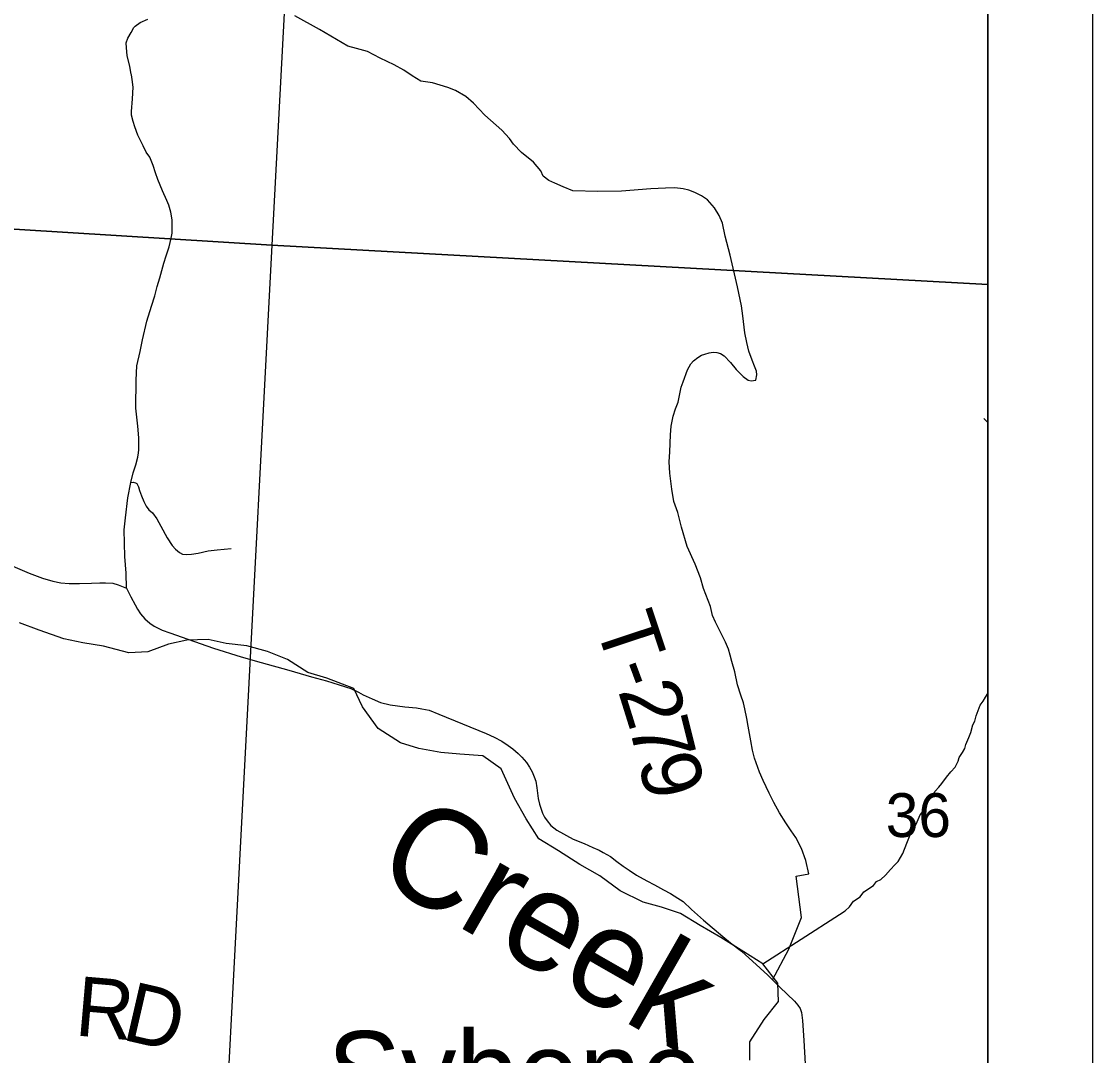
# Model space of a CAD drawing. Extents: x 0 to 45.4, y -2.2 to 22.
# Drawn here: x 7.977 to 9, y 15.245 to 16.232 of the extents above; entities that cross this region are included whole.
import ezdxf

# ---------------------------------------------------------------- set-up
doc = ezdxf.new("R2010")
doc.units = 0
for name, color, linetype in [('GM_X_Corporation', 7, 'Continuous'), ('GM_X_County_Road', 7, 'Continuous'), ('GM_X_Minor_River', 7, 'Continuous'), ('GM_X_Minor_River_Text', 7, 'Continuous'), ('GM_X_Section_Text', 7, 'Continuous'), ('GM_X_Township_Road', 7, 'Continuous'), ('GM_X_Township_Road_Text', 7, 'Continuous'), ('GM_X_Unincorporated_Text', 7, 'Continuous'), ('SH_Data', 7, 'Continuous')]:
    doc.layers.add(name, color=color, linetype=linetype)

msp = doc.modelspace()

# ---------------------------------------------------------------- linework, layer by layer
at = {"layer": 'GM_X_Corporation'}
for points in [[(5.6021, 14.1), (7.0413, 14.1), (7.1146, 14.1136), (7.5608, 14.2194), (7.6244, 14.2444), (8.0832, 14.3972), (8.4711, 14.5406), (8.5907, 14.5823), (8.8228, 14.6772), (8.9, 14.7192), (8.9, 20.9), (2.1, 20.9)], [(5.6021, 14.1), (7.0413, 14.1), (7.1146, 14.1136), (7.5608, 14.2194), (7.6244, 14.2444), (8.0832, 14.3972), (8.4711, 14.5406), (8.5907, 14.5823), (8.8228, 14.6772), (8.9, 14.7192), (8.9, 20.9), (6.2942, 20.9), (6.2882, 20.8226), (6.2789, 20.7002), (6.2588, 20.2929), (6.2538, 20.2076), (6.2346, 20.0088), (6.2236, 19.8542), (6.181, 19.2539), (6.1763, 19.1885), (6.1061, 18.1607), (5.642, 18.1908)]]:
    msp.add_lwpolyline(points, dxfattribs=at)
for points in [[(8.2701, 17.0306), (8.2164, 16.0186), (7.1036, 16.0876), (7.1661, 17.098)], [(8.9, 15.9811), (8.9, 16.9941), (8.2701, 17.0306), (8.2164, 16.0186)], [(7.1036, 16.0876), (8.2164, 16.0186), (8.1634, 15.0131), (7.0412, 15.0748)], [(8.9, 14.9765), (8.9, 15.9811), (8.2164, 16.0186), (8.1634, 15.0131)]]:
    msp.add_lwpolyline(points, close=True, dxfattribs=at)
at = {"layer": 'GM_X_County_Road'}
msp.add_lwpolyline([(7.9644, 15.7141), (7.9844, 15.7055), (7.9974, 15.7006), (8.0071, 15.6978), (8.0149, 15.6961), (8.0227, 15.6954), (8.0325, 15.6954), (8.044, 15.6958), (8.0521, 15.6963), (8.0573, 15.6962), (8.0643, 15.6958), (8.0694, 15.6943), (8.0774, 15.6911), (8.0817, 15.6829), (8.0857, 15.6753), (8.088, 15.671), (8.0909, 15.6665), (8.0951, 15.6619), (8.0998, 15.6578), (8.1038, 15.6549), (8.1114, 15.6511), (8.1188, 15.6483), (8.136, 15.6423), (8.1605, 15.6338), (8.1869, 15.6256), (8.2061, 15.62), (8.2324, 15.6127), (8.2542, 15.6064), (8.2683, 15.6025), (8.2807, 15.5989), (8.2917, 15.5953), (8.2989, 15.5918), (8.3035, 15.5893), (8.312, 15.5853), (8.3201, 15.582), (8.3293, 15.5798), (8.3433, 15.5779), (8.3544, 15.5769), (8.3596, 15.576), (8.3664, 15.5745), (8.3756, 15.5707), (8.421, 15.5523), (8.4285, 15.5489), (8.4359, 15.5449), (8.442, 15.5409), (8.4464, 15.5377), (8.4516, 15.5334), (8.4551, 15.5297), (8.4593, 15.5245), (8.4624, 15.5201), (8.4649, 15.5159), (8.4669, 15.511), (8.4683, 15.5067), (8.4694, 15.5005), (8.4707, 15.4902), (8.472, 15.4848), (8.4733, 15.48), (8.4748, 15.4763), (8.4765, 15.4726), (8.4791, 15.469), (8.4826, 15.4646), (8.4883, 15.4602), (8.5041, 15.4514), (8.5145, 15.4472), (8.5229, 15.4434), (8.5287, 15.4409), (8.5328, 15.4388), (8.5395, 15.4348), (8.5457, 15.4302), (8.5516, 15.4258), (8.5575, 15.4218), (8.5646, 15.4172), (8.5744, 15.4117), (8.5816, 15.4078), (8.5903, 15.4032), (8.5971, 15.3995), (8.6003, 15.3974), (8.6041, 15.395), (8.6091, 15.3918), (8.617, 15.3843), (8.6284, 15.3742), (8.6468, 15.3587), (8.6543, 15.3526), (8.6646, 15.3445), (8.6825, 15.3284), (8.6898, 15.3215), (8.6944, 15.3173), (8.7014, 15.3102), (8.7153, 15.2968), (8.7186, 15.2929), (8.7207, 15.2898), (8.7222, 15.286), (8.7225, 15.2836), (8.7229, 15.2785), (8.7243, 15.2592), (8.7256, 15.2369)], dxfattribs=at)
at = {"layer": 'GM_X_Minor_River'}
msp.add_line((8.9, 15.8494), (8.8961, 15.8532), dxfattribs=at)
for points in [[(8.6726, 15.2405), (8.6726, 15.258), (8.6864, 15.2792), (8.7001, 15.2966), (8.6994, 15.3141), (8.6851, 15.3324), (8.6669, 15.3439), (8.645, 15.3576), (8.6254, 15.3691), (8.6065, 15.3806), (8.5883, 15.3867), (8.5709, 15.3913), (8.549, 15.402), (8.5294, 15.4166), (8.5105, 15.4273), (8.4901, 15.4403), (8.4712, 15.4517), (8.4592, 15.4708), (8.4479, 15.4906), (8.4351, 15.5187), (8.4178, 15.531), (8.3958, 15.5326), (8.3776, 15.5341), (8.3565, 15.538), (8.3391, 15.5434), (8.3179, 15.5572), (8.3028, 15.5778), (8.2946, 15.5953), (8.2689, 15.6052), (8.2507, 15.6106), (8.2311, 15.6229), (8.2122, 15.6305), (8.1925, 15.6359), (8.1728, 15.6383), (8.1554, 15.6422), (8.135, 15.6415), (8.1175, 15.6377), (8.0978, 15.6302), (8.0796, 15.6295), (8.0554, 15.6357), (8.0357, 15.6388), (8.0176, 15.6427), (7.9941, 15.6511), (7.9752, 15.658)], [(8.6851, 15.3324), (8.7583, 15.3796), (8.7636, 15.3829), (8.7679, 15.387), (8.7717, 15.3923), (8.7782, 15.3963), (8.7817, 15.4012), (8.7909, 15.4071), (8.7936, 15.4109), (8.7979, 15.4131), (8.8021, 15.4172), (8.8071, 15.4224), (8.8113, 15.4269), (8.8144, 15.4303), (8.8187, 15.4378), (8.8227, 15.4476), (8.8259, 15.4556), (8.8294, 15.4612), (8.8317, 15.4657), (8.8353, 15.4748), (8.8384, 15.4785), (8.8419, 15.4868), (8.8466, 15.4917), (8.8497, 15.4974), (8.8532, 15.5011), (8.8559, 15.5045), (8.8605, 15.5105), (8.8648, 15.5157), (8.8687, 15.5202), (8.8718, 15.5259), (8.8726, 15.5293), (8.8757, 15.5342), (8.8781, 15.5379), (8.8789, 15.5417), (8.8817, 15.5485), (8.8836, 15.5534), (8.8857, 15.5606), (8.8876, 15.564), (8.8888, 15.5693), (8.8928, 15.5795), (8.8955, 15.5832), (8.8979, 15.587), (8.9, 15.5906)]]:
    msp.add_lwpolyline(points, dxfattribs=at)
at = {"layer": 'GM_X_Township_Road'}
for points in [[(8.0774, 15.6911), (8.077, 15.7055), (8.0759, 15.7214), (8.0753, 15.7469), (8.0764, 15.7582), (8.0786, 15.7772), (8.0816, 15.7919), (8.0838, 15.8011), (8.0864, 15.8087), (8.0884, 15.8162), (8.0889, 15.8202), (8.0892, 15.8233), (8.0893, 15.8275), (8.0891, 15.8346), (8.0884, 15.8456), (8.0864, 15.8629), (8.0865, 15.8728), (8.0866, 15.8802), (8.0867, 15.8898), (8.0873, 15.9035), (8.0904, 15.917), (8.0929, 15.9283), (8.0968, 15.946), (8.1013, 15.9604), (8.1044, 15.9702), (8.1069, 15.9792), (8.1092, 15.9874), (8.1131, 16.0013), (8.1154, 16.0085), (8.1181, 16.0169), (8.1202, 16.0251), (8.1211, 16.0301), (8.1211, 16.0366), (8.1211, 16.0426), (8.1197, 16.05), (8.1179, 16.0566), (8.116, 16.0613), (8.112, 16.0705), (8.1075, 16.0812), (8.1052, 16.0876), (8.1029, 16.0945), (8.0997, 16.1025), (8.0963, 16.1073), (8.0933, 16.1133), (8.0884, 16.1237), (8.0854, 16.1314), (8.0837, 16.1366), (8.0822, 16.1427), (8.0821, 16.146), (8.0831, 16.1581), (8.0837, 16.1693), (8.0829, 16.1767), (8.0821, 16.1812), (8.082, 16.1817), (8.0807, 16.1892), (8.0782, 16.1997), (8.0774, 16.2069), (8.0773, 16.2117), (8.0786, 16.2162), (8.0818, 16.2217), (8.0845, 16.2263), (8.0856, 16.2276), (8.0906, 16.231), (8.0979, 16.2343)], [(8.4546, 16.1069), (8.4471, 16.115), (8.4433, 16.1204), (8.436, 16.1284), (8.4198, 16.1427), (8.4089, 16.1541), (8.4015, 16.1605), (8.3918, 16.1661), (8.3844, 16.169), (8.3696, 16.1735), (8.3584, 16.175), (8.3502, 16.1802), (8.3422, 16.1857), (8.3331, 16.1907), (8.3198, 16.1972), (8.3076, 16.2034), (8.297, 16.2062), (8.2887, 16.2085), (8.2619, 16.2243), (8.2383, 16.2374)], [(8.6944, 15.3173), (8.7101, 15.3463), (8.7219, 15.3766), (8.7207, 15.3865), (8.717, 15.4161), (8.729, 15.4184), (8.7262, 15.4312), (8.7219, 15.4426), (8.7165, 15.453), (8.7123, 15.4595), (8.707, 15.4672), (8.7011, 15.4765), (8.6957, 15.4864), (8.6912, 15.4955), (8.6854, 15.5076), (8.6819, 15.5155), (8.6772, 15.5289), (8.6751, 15.5364), (8.6738, 15.5453), (8.6711, 15.5595), (8.6699, 15.5668), (8.6679, 15.5759), (8.6667, 15.5815), (8.6641, 15.5889), (8.6609, 15.5989), (8.6583, 15.6112), (8.6554, 15.621), (8.654, 15.6271), (8.6524, 15.6327), (8.6496, 15.6396), (8.6462, 15.6459), (8.642, 15.6541), (8.6399, 15.6585), (8.6372, 15.665), (8.6351, 15.6737), (8.6286, 15.6909), (8.6257, 15.701), (8.6206, 15.714), (8.613, 15.731), (8.6074, 15.7492), (8.6038, 15.7634), (8.6, 15.7737), (8.5982, 15.7856), (8.5962, 15.801), (8.5957, 15.8117), (8.5962, 15.8211), (8.5968, 15.8374), (8.5975, 15.8459), (8.5996, 15.8553), (8.6018, 15.8622), (8.6042, 15.8688), (8.607, 15.8831), (8.6089, 15.8881), (8.6131, 15.8994), (8.6165, 15.9051), (8.6189, 15.9081), (8.6231, 15.9114), (8.6266, 15.9135), (8.6297, 15.9146), (8.6338, 15.9159), (8.6376, 15.9164), (8.6412, 15.9161), (8.6446, 15.9152), (8.6481, 15.9128), (8.6541, 15.9066), (8.6598, 15.8997), (8.6663, 15.8931), (8.671, 15.8896), (8.6741, 15.8889), (8.6784, 15.8896), (8.6795, 15.8948), (8.679, 15.8981), (8.6772, 15.9029), (8.6748, 15.9086), (8.6716, 15.9172), (8.6698, 15.9257), (8.668, 15.9349), (8.666, 15.951), (8.6649, 15.9607), (8.6608, 15.9787), (8.6539, 16.0089), (8.6491, 16.0272), (8.6466, 16.0395), (8.6434, 16.0469), (8.6391, 16.0541), (8.6322, 16.0619), (8.6266, 16.0656), (8.6202, 16.0689), (8.6144, 16.0709), (8.609, 16.0722), (8.6011, 16.0734), (8.5922, 16.073), (8.5781, 16.0724), (8.55, 16.0701), (8.5276, 16.0697), (8.5036, 16.0704), (8.4946, 16.0742), (8.4865, 16.0776), (8.4809, 16.0804), (8.4752, 16.0844), (8.4732, 16.0895), (8.4661, 16.0977), (8.4546, 16.1069)], [(8.0816, 15.7919), (8.0838, 15.7924), (8.086, 15.7917), (8.0873, 15.791), (8.0888, 15.7877), (8.0898, 15.7844), (8.0917, 15.7791), (8.094, 15.7739), (8.0962, 15.7694), (8.0987, 15.766), (8.1022, 15.763), (8.1064, 15.7572), (8.1101, 15.7504), (8.1163, 15.7391), (8.121, 15.7317), (8.1242, 15.7282), (8.1281, 15.7251), (8.131, 15.7237), (8.1348, 15.7231), (8.1396, 15.7235), (8.146, 15.7245), (8.1556, 15.7267), (8.164, 15.7277), (8.1775, 15.7291)]]:
    msp.add_lwpolyline(points, dxfattribs=at)
at = {"layer": 'SH_Data'}
for p, q in [((9, 21), (9, 14)), ((8.9, 20.9), (8.9, 14.1))]:
    msp.add_line(p, q, dxfattribs=at)

# ---------------------------------------------------------------- texts
at = {"layer": 'GM_X_Minor_River_Text'}
msp.add_text('Creek', height=0.09471, rotation=330.2117, dxfattribs=at).set_placement((8.3114, 15.4155))
at = {"layer": 'GM_X_Section_Text'}
msp.add_text('36', height=0.04186, rotation=0, dxfattribs=at).set_placement((8.8025, 15.4535))
at = {"layer": 'GM_X_Township_Road_Text'}
for s, rotation, p in [('T', 288.3367, (8.5246, 15.6569)), ('-', 290.4631, (8.5388, 15.6144)), ('2', 287.3429, (8.5466, 15.5933)), ('7', 283.9807, (8.5568, 15.5608)), ('9', 284.5034, (8.5654, 15.5262)), ('R', 355.0227, (8.0273, 15.2642)), ('D', 347.0139, (8.0717, 15.2605))]:
    msp.add_text(s, height=0.0568, rotation=rotation, dxfattribs=at).set_placement(p)
at = {"layer": 'GM_X_Unincorporated_Text'}
msp.add_text('Sybene', height=0.07898, rotation=0, dxfattribs=at).set_placement((8.2692, 15.1892))

doc.saveas('drawing.dxf')
